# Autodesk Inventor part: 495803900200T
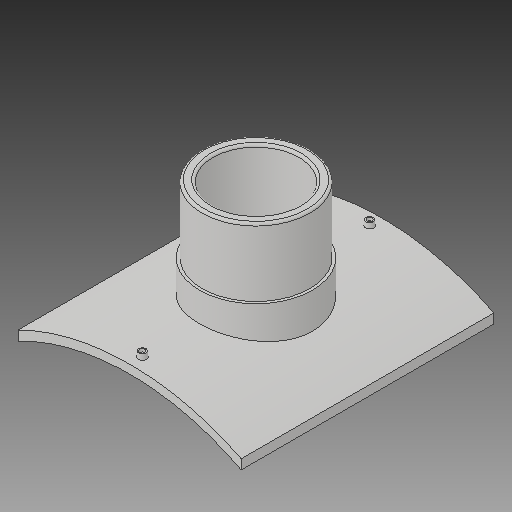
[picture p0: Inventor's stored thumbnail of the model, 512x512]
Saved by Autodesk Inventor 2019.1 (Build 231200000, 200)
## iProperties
Created: 2017-10
Part Number: 495803900200T
Material: Generic
Description: PLASSON BRANCH SADDLE  900x200
Document SubType Name: Modeling
Designer: KIM
Mass: 2754.05 g
Surface Area: 3037.44 cm^2
Volume: 2754.05 cm^3
Density: 1 g/cm^3
Appearance: Default
Author: KIM
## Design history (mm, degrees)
derived "495803.ipt"
feature "Solid1::495803.ipt"
tag "TaggingFeature1"
body "Solid1"
other parameters: "d1" = 16, "d2" = 415, "d4" = 0, "d12" = 475.6, "d13" = 14, "d14" = 211.5, "d16" = 5 deg, "d18" = 4, "d19" = 14, "d20" = 0, "d21" = 3, "d22" = 0, "d23" = 646, "d25" = 16, "d28" = 0, "d29" = 9.6, "d31" = 0, "d33" = 0, "d34" = 9, "d37" = 126, "d38" = 0, "d39" = 4.5, "B_" = 415, "x_" = 16, "D_" = 16
